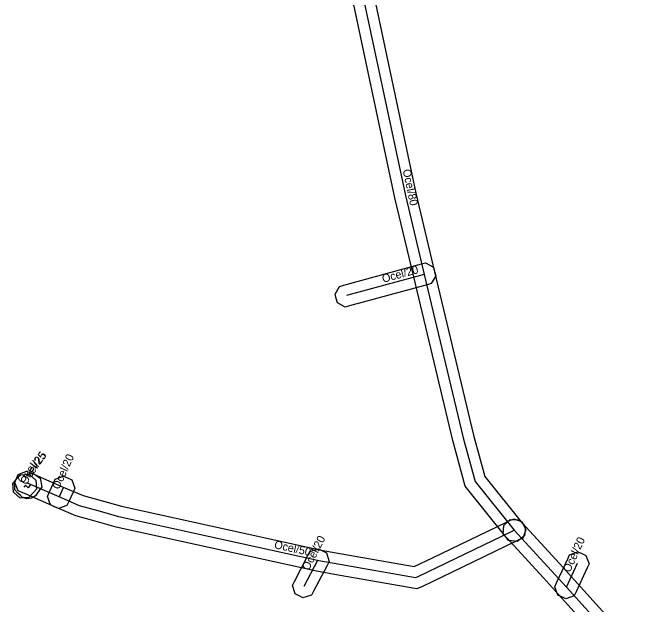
# Model space of a CAD drawing. Extents: x -569373 to -565022, y -1135090 to -1131496.
# Drawn here: x -565483.9 to -565424.2, y -1133846.6 to -1133791.5 of the extents above; entities that cross this region are included whole.
import ezdxf

# ---------------------------------------------------------------- set-up
doc = ezdxf.new("R2010")
doc.units = 0
for name, color, linetype in [('1', 7, 'Continuous'), ('24', 7, 'Continuous'), ('30', 7, 'Continuous')]:
    doc.layers.add(name, color=color, linetype=linetype)

msp = doc.modelspace()

# ---------------------------------------------------------------- linework, layer by layer
at = {"layer": '1'}
msp.add_lwpolyline([(-565450.762, -1133787.663), (-565446.374, -1133808.32), (-565444.627, -1133815.658), (-565440.991, -1133830.873), (-565439.949, -1133834.728), (-565436.429, -1133839.125), (-565436.17, -1133839.449), (-565436.261, -1133840.272), (-565436.585, -1133840.531), (-565436.909, -1133840.79), (-565437.732, -1133840.699), (-565437.991, -1133840.375), (-565441.771, -1133835.652), (-565442.929, -1133831.367), (-565446.573, -1133816.122), (-565448.326, -1133808.76), (-565452.718, -1133788.077)], dxfattribs=at)
for points in [[(-565444.936, -1133816.745), (-565445.336, -1133816.854), (-565452.566, -1133818.834), (-565452.965, -1133818.944), (-565453.685, -1133818.534), (-565453.794, -1133818.134), (-565453.904, -1133817.735), (-565453.494, -1133817.015), (-565453.094, -1133816.906), (-565445.864, -1133814.926), (-565445.465, -1133814.816), (-565444.745, -1133815.226), (-565444.636, -1133815.626), (-565444.526, -1133816.025)], [(-565481.734, -1133835.907), (-565482.007, -1133836.219), (-565482.147, -1133836.379), (-565482.42, -1133836.69), (-565483.247, -1133836.746), (-565483.559, -1133836.473), (-565483.87, -1133836.2), (-565483.926, -1133835.373), (-565483.653, -1133835.061), (-565483.513, -1133834.901), (-565483.24, -1133834.59), (-565482.413, -1133834.534), (-565482.101, -1133834.807), (-565481.79, -1133835.08)], [(-565483.194, -1133834.568), (-565482.819, -1133834.561), (-565482.065, -1133834.421), (-565481.723, -1133834.656), (-565481.382, -1133834.89), (-565481.231, -1133835.705), (-565481.466, -1133836.047), (-565481.686, -1133836.367), (-565481.811, -1133836.548), (-565482.189, -1133836.773), (-565482.408, -1133836.795), (-565482.627, -1133836.817), (-565483.044, -1133836.674), (-565483.203, -1133836.521), (-565483.453, -1133836.281), (-565483.752, -1133835.994), (-565483.768, -1133835.166), (-565483.481, -1133834.867)], [(-565453.276, -1133841.953), (-565446.544, -1133843.141), (-565444.825, -1133842.31), (-565437.939, -1133838.987), (-565437.633, -1133838.844), (-565437.258, -1133838.669), (-565436.479, -1133838.952), (-565436.304, -1133839.327), (-565436.129, -1133839.702), (-565436.412, -1133840.481), (-565436.787, -1133840.656), (-565437.081, -1133840.793), (-565443.955, -1133844.11), (-565445.765, -1133844.985), (-565446.278, -1133845.219), (-565453.624, -1133843.923), (-565455.629, -1133843.569), (-565455.769, -1133843.534), (-565474.292, -1133839.461), (-565476.25, -1133838.913), (-565478.055, -1133838.405), (-565480.017, -1133837.558), (-565482.688, -1133836.398), (-565483.057, -1133836.238), (-565483.437, -1133836.074), (-565483.742, -1133835.303), (-565483.578, -1133834.923), (-565483.414, -1133834.543), (-565482.643, -1133834.238), (-565482.263, -1133834.402), (-565481.892, -1133834.562), (-565479.223, -1133835.722), (-565477.385, -1133836.515), (-565475.71, -1133836.987), (-565473.808, -1133837.519), (-565455.311, -1133841.586), (-565455.211, -1133841.611)], [(-565478.148, -1133835.816), (-565478.319, -1133836.193), (-565478.709, -1133837.053), (-565478.88, -1133837.43), (-565479.656, -1133837.722), (-565480.033, -1133837.551), (-565480.41, -1133837.38), (-565480.702, -1133836.604), (-565480.531, -1133836.227), (-565480.141, -1133835.367), (-565479.97, -1133834.99), (-565479.194, -1133834.698), (-565478.817, -1133834.869), (-565478.44, -1133835.04)], [(-565436.756, -1133838.768), (-565436.475, -1133839.072), (-565432.99, -1133842.847), (-565431.606, -1133844.391), (-565425.809, -1133850.818), (-565422.746, -1133853.99), (-565421.602, -1133855.074), (-565421.301, -1133855.359), (-565421.279, -1133856.187), (-565421.564, -1133856.488), (-565421.849, -1133856.789), (-565422.677, -1133856.811), (-565422.978, -1133856.526), (-565424.154, -1133855.41), (-565427.271, -1133852.182), (-565433.094, -1133845.729), (-565434.47, -1133844.193), (-565437.945, -1133840.428), (-565438.226, -1133840.124), (-565438.192, -1133839.296), (-565437.888, -1133839.015), (-565437.584, -1133838.734)], [(-565454.462, -1133842.655), (-565454.653, -1133843.022), (-565455.913, -1133845.442), (-565456.104, -1133845.809), (-565456.895, -1133846.058), (-565457.262, -1133845.867), (-565457.629, -1133845.676), (-565457.878, -1133844.885), (-565457.687, -1133844.518), (-565456.427, -1133842.098), (-565456.236, -1133841.731), (-565455.445, -1133841.482), (-565455.078, -1133841.673), (-565454.711, -1133841.864)], [(-565433.432, -1133845.017), (-565433.258, -1133844.641), (-565432.228, -1133842.411), (-565432.054, -1133842.035), (-565431.277, -1133841.748), (-565430.901, -1133841.922), (-565430.525, -1133842.096), (-565430.238, -1133842.873), (-565430.412, -1133843.249), (-565431.442, -1133845.479), (-565431.616, -1133845.855), (-565432.393, -1133846.142), (-565432.769, -1133845.968), (-565433.145, -1133845.794)]]:
    msp.add_lwpolyline(points, close=True, dxfattribs=at)
at = {"layer": '24'}
for points in [[(-565454.04, -1133771.35), (-565453.38, -1133776.77), (-565452.44, -1133784.56), (-565451.74, -1133787.87), (-565447.35, -1133808.54), (-565445.6, -1133815.89), (-565441.96, -1133831.12), (-565440.86, -1133835.19), (-565437.21, -1133839.75)], [(-565445.6, -1133815.89), (-565452.83, -1133817.87)], [(-565437.21, -1133839.75), (-565437.51, -1133839.89), (-565444.39, -1133843.21), (-565446.19, -1133844.08), (-565446.41, -1133844.18), (-565453.45, -1133842.938), (-565455.42, -1133842.59), (-565455.54, -1133842.56), (-565474.05, -1133838.49), (-565475.98, -1133837.95), (-565477.72, -1133837.46), (-565479.62, -1133836.64), (-565482.29, -1133835.48), (-565482.66, -1133835.32)], [(-565482.76, -1133835.56), (-565482.9, -1133835.72)], [(-565482.29, -1133835.48), (-565482.51, -1133835.8), (-565482.76, -1133835.56)], [(-565479.23, -1133835.78), (-565479.62, -1133836.64)], [(-565437.21, -1133839.75), (-565433.73, -1133843.52), (-565432.35, -1133845.06), (-565426.54, -1133851.5), (-565423.45, -1133854.7), (-565422.29, -1133855.8)], [(-565455.54, -1133842.56), (-565456.8, -1133844.98)], [(-565432.35, -1133845.06), (-565431.32, -1133842.83)]]:
    msp.add_lwpolyline(points, dxfattribs=at)

# ---------------------------------------------------------------- texts
at = {"layer": '30'}
for s, rotation, p in [('Ocel/80', 281.9906, (-565447.612, -1133806.164)), ('Ocel/20', 15.31545, (-565449.415, -1133816.68)), ('Ocel/25', 48.81407, (-565483.03, -1133835.44)), ('Ocel/25', 55.49148, (-565482.698, -1133835.583)), ('Ocel/20', 65.60626, (-565479.625, -1133836.01)), ('Ocel/20', 62.49576, (-565456.37, -1133843.57)), ('Ocel/20', 65.20857, (-565432.035, -1133843.745)), ('Ocel/50', 347.59908, (-565459.62, -1133841.419))]:
    msp.add_text(s, height=0.75, rotation=rotation, dxfattribs=at).set_placement(p)

doc.saveas('drawing.dxf')
